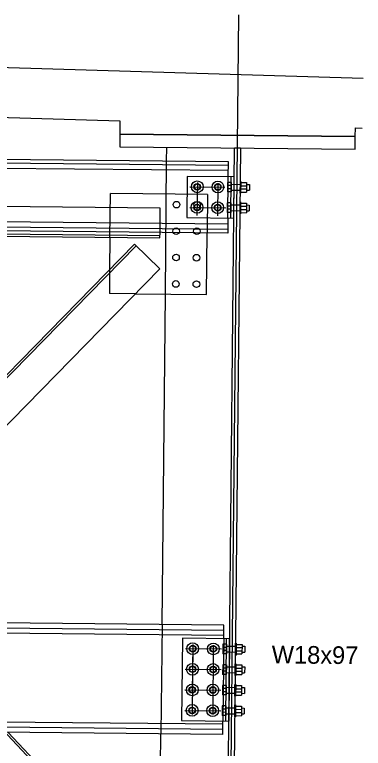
# Model space of a CAD drawing. Extents: x 632312 to 632885, y 378199 to 378534.
# Drawn here: x 632372.21 to 632377.15, y 378385.31 to 378395.71 of the extents above; entities that cross this region are included whole.
import ezdxf

# ---------------------------------------------------------------- set-up
doc = ezdxf.new("R2010")
doc.units = 0
for name, color, linetype in [('B_Boring', 7, 'Continuous'), ('B_Boring Annot', 7, 'Continuous'), ('R_Proposed Const Limits Cut', 7, 'Continuous'), ('R_Shade Removal', 7, 'Continuous'), ('R_Wall', 7, 'Continuous'), ('SHT_Dimensions', 7, 'Continuous')]:
    doc.layers.add(name, color=color, linetype=linetype)

msp = doc.modelspace()

# ---------------------------------------------------------------- linework, layer by layer
at = {"layer": 'B_Boring'}
for p, q in [((632374.361, 378393.627), (632374.363, 378393.826)), ((632375.236, 378393.619), (632364.237, 378393.728)), ((632375.236, 378393.568), (632364.236, 378393.678)), ((632375.234, 378393.406), (632375.236, 378393.619)), ((632374.651, 378393.412), (632374.645, 378392.829)), ((632375.318, 378393.405), (632374.651, 378393.412)), ((632375.27, 378392.823), (632375.276, 378393.406)), ((632375.312, 378392.822), (632375.318, 378393.405)), ((632375.223, 378393.328), (632375.222, 378393.193)), ((632375.275, 378393.328), (632375.223, 378393.328)), ((632375.275, 378393.328), (632375.274, 378393.192)), ((632375.4, 378393.342), (632375.399, 378393.175)), ((632375.4, 378393.342), (632375.411, 378393.342)), ((632375.411, 378393.342), (632375.409, 378393.175)), ((632375.411, 378393.326), (632375.494, 378393.326)), ((632375.494, 378393.326), (632375.493, 378393.19)), ((632375.494, 378393.299), (632375.535, 378393.299)), ((632375.535, 378393.299), (632375.534, 378393.216)), ((632375.274, 378393.237), (632375.222, 378393.238)), ((632375.274, 378393.192), (632375.222, 378393.193)), ((632375.275, 378393.283), (632375.223, 378393.283)), ((632375.409, 378393.191), (632375.493, 378393.19)), ((632375.41, 378393.281), (632375.493, 378393.28)), ((632375.41, 378393.236), (632375.493, 378393.235)), ((632375.493, 378393.216), (632375.534, 378393.216)), ((632373.565, 378393.168), (632373.565, 378393.168)), ((632375.399, 378393.175), (632375.409, 378393.175)), ((632375.22, 378393.037), (632375.219, 378392.901)), ((632375.272, 378393.036), (632375.22, 378393.037)), ((632375.272, 378392.991), (632375.22, 378392.991)), ((632375.272, 378393.036), (632375.271, 378392.901)), ((632375.397, 378393.05), (632375.396, 378392.884)), ((632375.397, 378393.05), (632375.408, 378393.05)), ((632375.408, 378393.05), (632375.406, 378392.884)), ((632375.407, 378392.99), (632375.491, 378392.989)), ((632375.408, 378393.035), (632375.491, 378393.034)), ((632375.491, 378393.034), (632375.49, 378392.898)), ((632375.491, 378393.008), (632375.532, 378393.007)), ((632375.532, 378393.007), (632375.532, 378392.924)), ((632375.271, 378392.946), (632375.219, 378392.946)), ((632375.271, 378392.901), (632375.219, 378392.901)), ((632375.396, 378392.884), (632375.406, 378392.884)), ((632375.406, 378392.899), (632375.49, 378392.898)), ((632375.407, 378392.944), (632375.49, 378392.944)), ((632375.49, 378392.925), (632375.532, 378392.924)), ((632375.227, 378392.661), (632364.227, 378392.77)), ((632374.645, 378392.829), (632375.312, 378392.822)), ((632375.228, 378392.823), (632375.226, 378392.61)), ((632375.226, 378392.61), (632364.227, 378392.72)), ((632369.726, 378392.589), (632374.267, 378392.544)), ((632374.267, 378392.544), (632374.268, 378392.62)), ((632374.926, 378391.737), (632374.935, 378392.613)), ((632373.916, 378391.747), (632374.926, 378391.737)), ((632374.296, 378387.06), (632374.343, 378391.743)), ((632375.171, 378387.051), (632364.172, 378387.16)), ((632375.17, 378386.978), (632364.171, 378387.088)), ((632375.169, 378386.859), (632375.171, 378387.051)), ((632374.586, 378386.865), (632374.574, 378385.698)), ((632375.252, 378386.858), (632374.586, 378386.865)), ((632375.199, 378385.692), (632375.211, 378386.859)), ((632375.252, 378386.858), (632375.241, 378385.692)), ((632375.158, 378386.781), (632375.157, 378386.646)), ((632375.21, 378386.781), (632375.158, 378386.781)), ((632375.21, 378386.736), (632375.158, 378386.736)), ((632375.251, 378386.754), (632375.335, 378386.753)), ((632375.334, 378386.628), (632375.335, 378386.795)), ((632375.335, 378386.795), (632375.346, 378386.795)), ((632375.346, 378386.795), (632375.344, 378386.628)), ((632375.345, 378386.779), (632375.429, 378386.779)), ((632375.345, 378386.734), (632375.428, 378386.733)), ((632375.429, 378386.779), (632375.427, 378386.643)), ((632375.429, 378386.752), (632375.47, 378386.752)), ((632375.47, 378386.752), (632375.469, 378386.669)), ((632375.209, 378386.69), (632375.157, 378386.691)), ((632375.209, 378386.645), (632375.157, 378386.646)), ((632375.251, 378386.671), (632375.334, 378386.67)), ((632375.344, 378386.644), (632375.427, 378386.643)), ((632375.345, 378386.689), (632375.428, 378386.688)), ((632375.428, 378386.669), (632375.469, 378386.669)), ((632375.334, 378386.628), (632375.344, 378386.628)), ((632375.155, 378386.49), (632375.154, 378386.354)), ((632375.207, 378386.489), (632375.155, 378386.49)), ((632375.207, 378386.444), (632375.155, 378386.444)), ((632375.331, 378386.337), (632375.332, 378386.503)), ((632375.332, 378386.503), (632375.343, 378386.503)), ((632375.343, 378386.503), (632375.341, 378386.337)), ((632375.342, 378386.443), (632375.425, 378386.442)), ((632375.343, 378386.488), (632375.426, 378386.487)), ((632375.426, 378386.487), (632375.425, 378386.351)), ((632375.426, 378386.461), (632375.467, 378386.46)), ((632375.467, 378386.46), (632375.466, 378386.377)), ((632375.206, 378386.399), (632375.154, 378386.399)), ((632375.206, 378386.354), (632375.154, 378386.354)), ((632375.331, 378386.337), (632375.341, 378386.337)), ((632375.341, 378386.352), (632375.425, 378386.351)), ((632375.342, 378386.397), (632375.425, 378386.397)), ((632375.425, 378386.377), (632375.466, 378386.377)), ((632375.152, 378386.198), (632375.151, 378386.063)), ((632375.204, 378386.197), (632375.152, 378386.198)), ((632375.204, 378386.152), (632375.152, 378386.153)), ((632375.328, 378386.045), (632375.329, 378386.212)), ((632375.329, 378386.212), (632375.34, 378386.212)), ((632375.34, 378386.212), (632375.338, 378386.045)), ((632375.339, 378386.151), (632375.423, 378386.15)), ((632375.34, 378386.196), (632375.423, 378386.195)), ((632375.423, 378386.195), (632375.422, 378386.06)), ((632375.423, 378386.169), (632375.464, 378386.169)), ((632375.464, 378386.169), (632375.464, 378386.085)), ((632375.203, 378386.107), (632375.151, 378386.108)), ((632375.203, 378386.062), (632375.151, 378386.063)), ((632375.328, 378386.045), (632375.338, 378386.045)), ((632375.338, 378386.061), (632375.422, 378386.06)), ((632375.339, 378386.106), (632375.422, 378386.105)), ((632375.422, 378386.086), (632375.464, 378386.085)), ((632375.149, 378385.906), (632375.148, 378385.771)), ((632375.201, 378385.906), (632375.149, 378385.906)), ((632375.325, 378385.753), (632375.327, 378385.92)), ((632375.327, 378385.92), (632375.337, 378385.92)), ((632375.337, 378385.92), (632375.335, 378385.753)), ((632375.337, 378385.904), (632375.42, 378385.904)), ((632375.42, 378385.904), (632375.419, 378385.768)), ((632375.2, 378385.815), (632375.148, 378385.816)), ((632375.201, 378385.861), (632375.149, 378385.861)), ((632375.336, 378385.859), (632375.42, 378385.858)), ((632375.336, 378385.814), (632375.419, 378385.813)), ((632375.42, 378385.878), (632375.461, 378385.877)), ((632375.461, 378385.877), (632375.461, 378385.794)), ((632374.574, 378385.698), (632375.241, 378385.692)), ((632375.2, 378385.77), (632375.148, 378385.771)), ((632375.325, 378385.753), (632375.335, 378385.753)), ((632375.335, 378385.769), (632375.419, 378385.768)), ((632375.419, 378385.794), (632375.461, 378385.794)), ((632375.156, 378385.501), (632364.156, 378385.61)), ((632375.156, 378385.573), (632364.157, 378385.683)), ((632375.156, 378385.501), (632375.158, 378385.693)), ((632374.263, 378383.702), (632374.281, 378385.51))]:
    msp.add_line(p, q, dxfattribs=at)
for points in [[(632377.03, 378393.8), (632377.032, 378393.977), (632373.699, 378394.01), (632373.697, 378393.833)], [(632375.286, 378381.817), (632375.202, 378381.817), (632375.322, 378393.817), (632375.405, 378393.816)]]:
    msp.add_lwpolyline(points, close=True, dxfattribs=at)
for points in [[(632373.559, 378392.551), (632373.554, 378392.093)], [(632370.486, 378388.235), (632374.263, 378392.103), (632373.905, 378392.452), (632370.491, 378388.956)], [(632372.118, 378385.531), (632374.176, 378383.339)]]:
    msp.add_lwpolyline(points, dxfattribs=at)
for centre in [(632374.795, 378393.265), (632375.087, 378393.262), (632374.501, 378393.012), (632374.793, 378393.01), (632374.792, 378392.973), (632375.084, 378392.97), (632374.497, 378392.637), (632374.789, 378392.635), (632374.494, 378392.263), (632374.785, 378392.26), (632374.49, 378391.888), (632374.782, 378391.885), (632374.73, 378386.718), (632375.022, 378386.715), (632374.727, 378386.426), (632375.019, 378386.423), (632374.724, 378386.134), (632375.016, 378386.132), (632374.722, 378385.843), (632375.013, 378385.84)]:
    msp.add_circle(centre, 0.0469, dxfattribs=at)
at = {"layer": 'B_Boring Annot'}
for p, q in [((632370.75, 378394.997), (632377.146, 378394.805)), ((632369.743, 378394.318), (632373.7, 378394.2)), ((632373.7, 378394.2), (632373.699, 378394.01)), ((632377.032, 378393.977), (632377.033, 378394.1)), ((632377.033, 378394.1), (632377.129, 378394.097)), ((632373.699, 378394.01), (632377.032, 378393.977))]:
    msp.add_line(p, q, dxfattribs=at)
at = {"layer": 'R_Proposed Const Limits Cut'}
for p, q in [((632375.235, 378393.494), (632364.236, 378393.603)), ((632374.343, 378391.743), (632374.361, 378393.627)), ((632375.228, 378392.823), (632375.234, 378393.406)), ((632375.275, 378393.302), (632375.4, 378393.3)), ((632375.274, 378393.218), (632375.399, 378393.217)), ((632373.559, 378392.551), (632373.565, 378393.168)), ((632374.94, 378393.154), (632373.565, 378393.168)), ((632374.94, 378393.154), (632374.935, 378392.613)), ((632374.271, 378392.961), (632365.189, 378393.051)), ((632375.272, 378393.01), (632375.397, 378393.009)), ((632374.268, 378392.62), (632374.271, 378392.961)), ((632375.271, 378392.927), (632375.396, 378392.925)), ((632375.228, 378392.735), (632364.228, 378392.845)), ((632374.268, 378392.57), (632365.185, 378392.66)), ((632365.522, 378392.514), (632374.153, 378383.318)), ((632373.928, 378392.43), (632365.115, 378383.408)), ((632373.554, 378392.093), (632373.551, 378391.751)), ((632373.916, 378391.747), (632373.551, 378391.751)), ((632374.296, 378387.06), (632374.281, 378385.51)), ((632375.17, 378386.905), (632364.17, 378387.014)), ((632375.169, 378386.859), (632375.158, 378385.693)), ((632375.21, 378386.755), (632375.251, 378386.754)), ((632375.209, 378386.671), (632375.251, 378386.671)), ((632375.207, 378386.463), (632375.332, 378386.462)), ((632375.206, 378386.38), (632375.331, 378386.378)), ((632375.204, 378386.171), (632375.329, 378386.17)), ((632375.203, 378386.088), (632375.328, 378386.087)), ((632375.201, 378385.88), (632375.326, 378385.878)), ((632375.157, 378385.647), (632364.158, 378385.756)), ((632375.2, 378385.796), (632375.325, 378385.795))]:
    msp.add_line(p, q, dxfattribs=at)
for centre, radius in [((632374.795, 378393.265), 0.0833), ((632374.795, 378393.265), 0.0417), ((632375.087, 378393.262), 0.0833), ((632375.087, 378393.262), 0.0417), ((632374.792, 378392.973), 0.0833), ((632374.792, 378392.973), 0.0417), ((632375.084, 378392.97), 0.0833), ((632375.084, 378392.97), 0.0417), ((632374.73, 378386.718), 0.0833), ((632374.73, 378386.718), 0.0417), ((632375.022, 378386.715), 0.0833), ((632375.022, 378386.715), 0.0417), ((632374.727, 378386.426), 0.0833), ((632374.727, 378386.426), 0.0417), ((632375.019, 378386.423), 0.0833), ((632375.019, 378386.423), 0.0417), ((632374.724, 378386.134), 0.0833), ((632375.016, 378386.132), 0.0833), ((632374.724, 378386.134), 0.0417), ((632375.016, 378386.132), 0.0417), ((632374.722, 378385.843), 0.0833), ((632375.013, 378385.84), 0.0833), ((632374.722, 378385.843), 0.0417), ((632375.013, 378385.84), 0.0417)]:
    msp.add_circle(centre, radius, dxfattribs=at)
at = {"layer": 'R_Shade Removal'}
msp.add_line((632375.232, 378380.64), (632375.382, 378395.705), dxfattribs=at)
at = {"layer": 'R_Wall'}
for p, q in [((632374.796, 378393.325), (632374.791, 378392.86)), ((632375.088, 378393.316), (632375.083, 378392.853)), ((632374.691, 378393.266), (632375.186, 378393.261)), ((632374.688, 378392.974), (632375.198, 378392.969)), ((632374.731, 378386.778), (632374.721, 378385.785)), ((632375.022, 378386.769), (632375.013, 378385.784)), ((632374.626, 378386.719), (632375.136, 378386.714)), ((632374.623, 378386.427), (632375.133, 378386.422)), ((632374.62, 378386.135), (632375.13, 378386.13)), ((632374.617, 378385.844), (632375.127, 378385.839))]:
    msp.add_line(p, q, dxfattribs=at)
at = {"layer": 'SHT_Dimensions'}
for p, q in [((632374.731, 378386.778), (632374.724, 378386.088)), ((632375.21, 378386.781), (632375.209, 378386.645)), ((632375.207, 378386.489), (632375.206, 378386.354)), ((632375.204, 378386.197), (632375.203, 378386.062)), ((632375.201, 378385.906), (632375.2, 378385.77))]:
    msp.add_line(p, q, dxfattribs=at)

# ---------------------------------------------------------------- texts
msp.add_text('W18x97', height=0.25, rotation=359.4304, dxfattribs=at).set_placement((632375.848, 378386.511))

doc.saveas('drawing.dxf')
